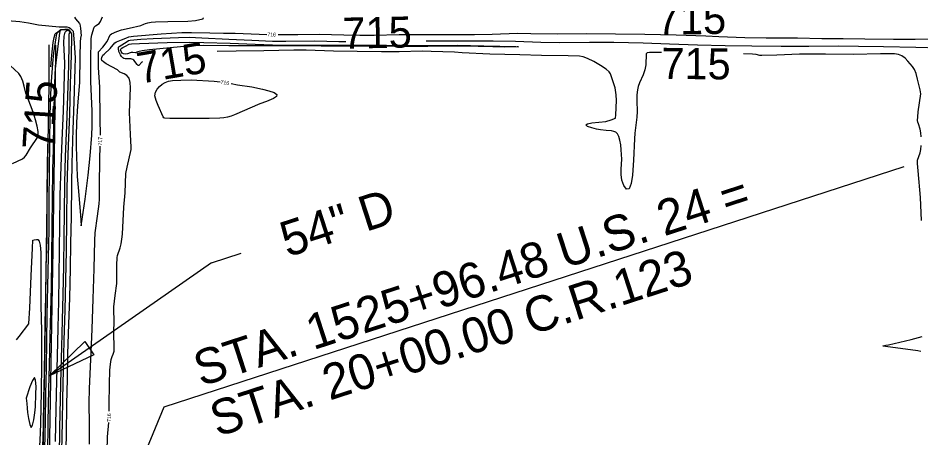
# Model space of a CAD drawing. Extents: x -468563856 to 36492962, y -306094093 to 11899197.
# Drawn here: x 1819091 to 1820050, y 530560 to 531006 of the extents above; entities that cross this region are included whole.
import ezdxf

# ---------------------------------------------------------------- set-up
doc = ezdxf.new("R2010")
doc.units = 0
for name, color, linetype in [('DT_X_Contour_Minor', 7, 'Continuous'), ('Level 19', 7, 'Continuous'), ('Level 40', 7, 'Continuous'), ('Level 56', 7, 'Continuous')]:
    doc.layers.add(name, color=color, linetype=linetype)

msp = doc.modelspace()

# ---------------------------------------------------------------- linework, layer by layer
at = {"layer": 'DT_X_Contour_Minor'}
for points in [[(1819080.31, 531003.25), (1819093.32, 531002.24), (1819102.49, 531000.93), (1819112.95, 530998.75), (1819123.96, 530997.52), (1819135.05, 530996.75), (1819143.11, 530996.66), (1819145.51, 530995.88), (1819147, 530994.88), (1819149.48, 530992.56), (1819149.75, 530992.14), (1819150.94, 530979.75), (1819151.96, 530963.61), (1819151.74, 530952.29), (1819150.58, 530917.11), (1819149.6, 530887.47), (1819148.32, 530851.32), (1819148.03, 530829.98), (1819147.6, 530794.77), (1819147.09, 530767.05), (1819146.57, 530739.96), (1819145.87, 530708.41), (1819145.06, 530681.06), (1819144.04, 530648.94), (1819143.44, 530622.57), (1819142.86, 530595.85), (1819142.3, 530563.39), (1819141.59, 530535.57)], [(1819151.2, 531006.75), (1819152.34, 531004.97), (1819156.66, 531000.33), (1819157.08, 530999.35), (1819157.7, 530995.22), (1819158.27, 530986.96), (1819158.04, 530986.37), (1819157.72, 530984.64), (1819157.41, 530980.57), (1819157.06, 530964.66), (1819156.66, 530937.45), (1819154.53, 530912.68), (1819153.43, 530895.11), (1819153.02, 530880.56), (1819153.11, 530869.68), (1819154.15, 530837.81), (1819155.4, 530821.95), (1819155.44, 530821.59)], [(1819155.44, 530821.59), (1819157.53, 530796.71), (1819158.48, 530785.45), (1819162.47, 530813.65), (1819165.84, 530839.19), (1819168.03, 530859.71), (1819169.82, 530881.48), (1819170.14, 530891.3), (1819169.9, 530907.06), (1819168.81, 530938.67), (1819168.68, 530960.15), (1819169.09, 530984.07), (1819169.72, 530988.06), (1819172.03, 530996.25), (1819173.62, 530997.52), (1819177.67, 531000.19), (1819179.04, 531002.13), (1819181.2, 531007.31)], [(1819178.76, 530881.74), (1819178.73, 530898.84), (1819178.05, 530932.58), (1819176.96, 530953.29), (1819176.97, 530969.95), (1819181.28, 530975.06), (1819186.16, 530980.98), (1819189.33, 530987.98), (1819190.6, 530989.13), (1819196.42, 530991.79), (1819201.22, 530993.46), (1819209.5, 530995.34), (1819221.72, 530997.98), (1819225.09, 530999.35), (1819226.84, 531000.16), (1819229.25, 531000.97), (1819232.69, 531001.61), (1819237.44, 531002), (1819250.3, 531002.27), (1819271.74, 531002.72), (1819279.97, 531003.52), (1819287.48, 531005.01), (1819288.3, 531005.54), (1819287.5, 531006.1)], [(1819138.56, 530685.04), (1819139.23, 530712.43), (1819139.82, 530742.62), (1819140.3, 530773.46), (1819140.66, 530798.58), (1819141.1, 530830.85), (1819141.84, 530859.05), (1819143.31, 530891.82), (1819144.33, 530923.36), (1819145.33, 530955.95), (1819145.79, 530978.81), (1819145.8, 530988.99), (1819146.41, 530990.98), (1819145.69, 530992.42), (1819144.59, 530993.77), (1819141.19, 530993.71), (1819136.58, 530993.47), (1819135.63, 530992.66), (1819132.23, 530989.11), (1819131.45, 530984.89), (1819129.14, 530968.96), (1819127.94, 530957.57), (1819126.46, 530938.57), (1819125.75, 530924.77), (1819125.23, 530902.82), (1819124.8, 530873.65), (1819124.46, 530842.84), (1819124.11, 530811.97), (1819123.95, 530780.38), (1819123.35, 530751.91), (1819122.79, 530721.27), (1819122.08, 530690.11), (1819121.64, 530664.16), (1819121.08, 530634.24), (1819120.55, 530606.52), (1819120, 530578.27), (1819119.3, 530547.97)], [(1819133.87, 530676.96), (1819134.57, 530705.41), (1819135.1, 530730.81), (1819135.5, 530760.39), (1819135.83, 530786.04), (1819136.27, 530818.03), (1819137, 530848.3), (1819138.05, 530876.44), (1819139.57, 530907.24), (1819140.31, 530932.33), (1819140.9, 530957.96), (1819140.03, 530979.7), (1819140.3, 530986.85), (1819141.34, 530990.85), (1819142.75, 530992.37), (1819144.74, 530993.05), (1819144.42, 530993.36), (1819136.72, 530993.07), (1819135.64, 530991.89), (1819135.16, 530987.28), (1819131.37, 530958.48), (1819130.62, 530951.92), (1819130.34, 530947.19), (1819129.58, 530922.95), (1819129.01, 530897.72), (1819128.5, 530866.1), (1819128.12, 530845.44), (1819127.55, 530812.9), (1819127.28, 530785.53), (1819126.84, 530750.76), (1819126.38, 530720.73), (1819125.75, 530693.9), (1819125.17, 530668.45), (1819124.48, 530637.31), (1819123.87, 530612.12), (1819123.04, 530576.32), (1819122.55, 530542.42)], [(1819126.13, 530954), (1819127.15, 530966.61), (1819128.7, 530979.97), (1819129.75, 530985.23), (1819130.96, 530989.1), (1819131.57, 530990.04), (1819133.36, 530991.07), (1819135.36, 530992.7), (1819136.7, 530993.74), (1819138.04, 530993.86), (1819144.9, 530993.87), (1819145.86, 530992.55), (1819148.05, 530989.13), (1819148.16, 530986.14), (1819147.78, 530966.46), (1819146.87, 530935.98), (1819145.87, 530903.96), (1819144.61, 530870.48), (1819143.79, 530850.11), (1819143.32, 530825.2), (1819142.89, 530791.28), (1819142.35, 530758.56), (1819141.82, 530728.05), (1819141.06, 530695.81), (1819140.09, 530663.49), (1819139.34, 530632.43), (1819138.61, 530601.67), (1819138.12, 530576.66), (1819137.58, 530546.32)], [(1819188.14, 530588.36), (1819188.26, 530595.02), (1819188.46, 530617.2), (1819189, 530631.93), (1819189.51, 530638.28), (1819190.3, 530643.24), (1819191.41, 530646.54), (1819192.55, 530649.08), (1819193.35, 530652.05), (1819193.56, 530656.29), (1819193.09, 530671.04), (1819193.38, 530685.6), (1819193.01, 530695.08), (1819193.2, 530699.41), (1819194.59, 530711.14), (1819196.19, 530724.05), (1819196.3, 530729.96), (1819196.22, 530743.67), (1819196.56, 530751.52), (1819197.01, 530753.64), (1819199.86, 530761.89), (1819200.86, 530766.11), (1819201.68, 530771.08), (1819202.23, 530776.54), (1819203.61, 530805), (1819204.98, 530820.18), (1819205.83, 530840.8), (1819207.14, 530847.62), (1819211.48, 530866.41), (1819211.62, 530868.72), (1819210.89, 530882.44), (1819209.74, 530905.56), (1819210.7, 530931.96), (1819210.41, 530937.61), (1819209.24, 530942.04), (1819206.95, 530944.92), (1819204.16, 530946.57), (1819199.36, 530948.48), (1819196.88, 530950.87), (1819185.04, 530957.46), (1819182, 530959.48), (1819180.35, 530961.01), (1819179.85, 530962.16), (1819180.36, 530964.11), (1819181.57, 530966.37), (1819182.91, 530967.73), (1819189.04, 530973.6), (1819194.2, 530979.75), (1819195.97, 530980.77), (1819201.29, 530982.72), (1819205.94, 530984.52), (1819208.97, 530986.15), (1819213.89, 530986.69), (1819243.47, 530989.1), (1819265.45, 530990.44), (1819275.62, 530990.7), (1819294.92, 530990.22), (1819309.48, 530989.81), (1819321.99, 530989.73), (1819347.55, 530988.68), (1819355.44, 530988.52)], [(1819367.44, 530988.41), (1819388.31, 530988.64), (1819411.18, 530988.73), (1819437.37, 530988.06), (1819454.31, 530987.73), (1819469.51, 530987.84), (1819496.24, 530988.38), (1819527.66, 530988.53), (1819559.81, 530988.48), (1819575.99, 530988.52), (1819594.74, 530988.91), (1819621.88, 530989.77), (1819636.04, 530989.7), (1819664.7, 530989.34), (1819695.1, 530989.44), (1819725.86, 530989.13), (1819757.08, 530988.76), (1819790.24, 530988.04), (1819821.59, 530987.14), (1819835.5, 530986.48), (1819863.05, 530985.14), (1819885.78, 530984.97), (1819918.92, 530984.85), (1819945.05, 530984.32), (1819967.53, 530984.12), (1819990.41, 530984), (1820020.89, 530983.63), (1820043.94, 530983.51), (1820075.99, 530983.99)], [(1819223.39, 530959.58), (1819222.72, 530959.08), (1819219.79, 530955.64), (1819218.85, 530955.52), (1819217.8, 530956.58), (1819214.49, 530961.32), (1819213.42, 530962.05), (1819211.06, 530962.6), (1819205.01, 530962.66), (1819203.76, 530963.08), (1819202.49, 530963.86), (1819201.27, 530965.06), (1819200.15, 530966.72), (1819198.53, 530970.54), (1819198.03, 530973.56), (1819198.16, 530975.07), (1819198.69, 530975.58), (1819207.19, 530981.09), (1819208.8, 530981.95), (1819210.36, 530982.35), (1819221.82, 530983.37), (1819234.92, 530984.08), (1819261.68, 530985.32), (1819273.2, 530985.57), (1819286.63, 530985.06), (1819315.28, 530983.65), (1819339.76, 530982.43), (1819361.52, 530981.46), (1819375.88, 530981.5), (1819406.59, 530981.85), (1819432.06, 530981.22), (1819439.59, 530981.06)], [(1819327.78, 530976.32), (1819315.06, 530976.36), (1819287.81, 530976.73), (1819276.23, 530976.47), (1819263.79, 530975.36), (1819231.13, 530972.14), (1819223.27, 530971.22), (1819218.42, 530970.07), (1819215.78, 530969.16), (1819213.39, 530969.29), (1819211.57, 530969.45), (1819210.25, 530969.04), (1819207.47, 530968.02), (1819205.14, 530967.65), (1819203.18, 530967.85), (1819201.83, 530968.82), (1819200.81, 530970.59), (1819200.31, 530972.38), (1819200.39, 530973.09), (1819200.78, 530973.68), (1819202.6, 530974.68), (1819205.36, 530976.12), (1819209.22, 530978.14), (1819211.79, 530978.54), (1819220.46, 530979.08), (1819249.57, 530979.86), (1819273.03, 530980.21), (1819288.82, 530979.87), (1819316.71, 530979.12), (1819343.03, 530978.11), (1819370.89, 530977.22), (1819398.1, 530977.16), (1819424.43, 530977.05), (1819453.87, 530977.09), (1819470.45, 530977.04), (1819494.09, 530976.79), (1819523.85, 530976.84), (1819557.73, 530977.24), (1819585.87, 530976.58), (1819619.93, 530975.73), (1819622.66, 530975.53), (1819621.32, 530975.34), (1819607.66, 530975.02), (1819595.52, 530975.25), (1819564.33, 530976.03), (1819553.32, 530976.23), (1819526.44, 530975.91), (1819500.02, 530975.7), (1819468.97, 530976.05), (1819442.86, 530976.15), (1819413.09, 530976.21), (1819385.99, 530976.37), (1819352.08, 530976.35), (1819327.78, 530976.32)], [(1819488.4, 530981.47), (1819488.78, 530981.48)], [(1819524.85, 530981.62), (1819546.69, 530981.85), (1819570.02, 530981.69), (1819595.74, 530981.59), (1819619.67, 530981.29), (1819646.62, 530980.33), (1819666.36, 530980.14), (1819698.01, 530980.47), (1819724.18, 530980.2), (1819755.23, 530979.76), (1819783.11, 530978.61), (1819812.82, 530977.62), (1819842.16, 530976.64), (1819870.43, 530976.38), (1819901.85, 530976.23), (1819931.2, 530976.23), (1819962.14, 530976.56), (1819983.87, 530976.21), (1820010.27, 530975.64), (1820044.52, 530975.05), (1820069.74, 530974.32)], [(1819774.46, 530969.5), (1819771.8, 530969.52), (1819761.82, 530969.31), (1819759.34, 530969.04), (1819758.42, 530968.06), (1819757.99, 530956.39), (1819757.06, 530950.87), (1819755.29, 530945.78), (1819751.16, 530937), (1819749.84, 530933.19), (1819749.09, 530929.79), (1819748.52, 530924.37), (1819748.57, 530918.03), (1819748.78, 530906.89), (1819748.53, 530900.68), (1819746.99, 530889.38), (1819746.23, 530883.73), (1819745.79, 530877.73), (1819745.04, 530855.08), (1819743.67, 530838.93), (1819742.32, 530830.18), (1819740.25, 530824.63), (1819737.44, 530824.37), (1819734.55, 530828.16), (1819732.41, 530833.92), (1819731.63, 530839.89), (1819731.79, 530845.64), (1819732.4, 530856.06), (1819731.88, 530865.89), (1819731.31, 530871.14), (1819730.5, 530876.17), (1819729.42, 530880.3), (1819728, 530883.05), (1819726.23, 530884.67), (1819724.1, 530885.58), (1819721.61, 530886.15), (1819716.02, 530886.7), (1819709.73, 530887.14), (1819705.56, 530887.89), (1819700.55, 530889.23), (1819696.17, 530890.88), (1819694.29, 530892.48), (1819696.17, 530893.7), (1819700.52, 530894.55), (1819715.68, 530896.15), (1819721.35, 530897.74), (1819725.74, 530899.47), (1819725.9, 530899.72), (1819726.19, 530903.3), (1819726.72, 530918.44), (1819726.49, 530924.43), (1819725.27, 530931.77), (1819723.35, 530938.23), (1819720.52, 530946.72), (1819719.13, 530948.99), (1819715.82, 530951.84), (1819709.88, 530955.65), (1819702.7, 530959.7), (1819696.17, 530963.02), (1819691.56, 530964.88), (1819687.67, 530965.6), (1819675.4, 530965.77), (1819647.32, 530966.08), (1819624.1, 530966.87), (1819592.33, 530967.75), (1819562.87, 530968.98), (1819554.84, 530969.57), (1819529.95, 530970.51), (1819520.57, 530970.64), (1819496.22, 530970.16), (1819477.33, 530969.92), (1819451.58, 530970.26), (1819426.21, 530970.73), (1819397.35, 530971.96), (1819384.05, 530971.89), (1819352.39, 530971.05), (1819323.11, 530970.72), (1819302.64, 530970.44)], [(1820041.23, 530954.39), (1820036.29, 530960.34), (1820033.24, 530963.43), (1820029.95, 530965.91), (1820026.41, 530967.35), (1820021.9, 530967.93), (1820007.09, 530967.81), (1819978.54, 530967.26), (1819948.77, 530967.52), (1819921.03, 530967.54), (1819897, 530966.61), (1819881.02, 530966.06), (1819878.95, 530966.33), (1819875.02, 530967.1), (1819871.25, 530967.51), (1819861.61, 530967.95)], [(1819085.52, 530851.42), (1819096.24, 530856.49), (1819098.29, 530858.3), (1819099.83, 530860.33), (1819104.43, 530868.13), (1819112.12, 530879.05), (1819112.76, 530881.63), (1819112.61, 530885.43), (1819111.64, 530891.03), (1819110.01, 530897.84), (1819107.88, 530904.96), (1819105.47, 530911.55), (1819099.5, 530926.12), (1819097.88, 530933.47), (1819096.37, 530939.02), (1819094.45, 530943.97), (1819092.17, 530947.23), (1819082.83, 530955.63)], [(1820050.46, 530879.72), (1820050.11, 530884.08), (1820049.45, 530887.93), (1820047.45, 530893.45), (1820046.68, 530895.42), (1820046.39, 530897.1), (1820046.69, 530901.19), (1820047.22, 530906.2), (1820049.99, 530925.41), (1820049.16, 530929.74), (1820046.57, 530941.22), (1820044.89, 530947.04), (1820043.14, 530951.28), (1820041.23, 530954.39)], [(1819317.67, 530936.3), (1819324.37, 530935.17), (1819339.75, 530932.91), (1819351.1, 530930.51), (1819357.61, 530928.84), (1819363.21, 530926.92), (1819366.25, 530924.79), (1819365.64, 530922.56), (1819362.52, 530920.43), (1819355.17, 530917.39), (1819348.29, 530914.87), (1819321.1, 530903.1), (1819317.52, 530901.78), (1819313.76, 530900.68), (1819309.86, 530899.98), (1819305.52, 530899.61), (1819294.26, 530899.36), (1819266.45, 530899.15), (1819252.54, 530899.14), (1819247.14, 530899.66), (1819246.33, 530900.09), (1819245.64, 530900.95), (1819240.12, 530913.07), (1819237.91, 530918.34), (1819236.7, 530923.33), (1819237.17, 530927.38), (1819238.97, 530930.61), (1819241.5, 530933.28), (1819244.3, 530935.6), (1819247.43, 530937.52), (1819251.07, 530938.9), (1819255.33, 530939.68), (1819264.25, 530940.15), (1819275.11, 530940.24), (1819299.62, 530939.06), (1819305.83, 530938.23)], [(1819117.67, 530550.74), (1819118.37, 530572.31), (1819118.88, 530602.07), (1819119.39, 530629.22), (1819119.75, 530655.31), (1819120.12, 530681.93), (1819120.75, 530710.58), (1819121.39, 530741.13), (1819122.15, 530771.23), (1819122.37, 530791.31), (1819122.4, 530823.97), (1819122.61, 530845.41), (1819122.87, 530872.07)], [(1819167.21, 530553.27), (1819167.2, 530574.75), (1819167, 530596.84), (1819167.3, 530612.44), (1819168.8, 530643.3), (1819169.94, 530675.58), (1819171.05, 530707.68), (1819172.19, 530739.54), (1819172.73, 530769.71), (1819173.33, 530777.95), (1819175.66, 530795.51), (1819177.5, 530808.61), (1819177.86, 530813.65), (1819178.02, 530827.98), (1819178.22, 530856.1), (1819178.54, 530869.74)], [(1820050.55, 530790.91), (1820049.53, 530815.45), (1820047.03, 530843.53), (1820046.54, 530851.64), (1820046.29, 530853.25), (1820046.43, 530855.07), (1820049.36, 530862.73), (1820050.08, 530866.43), (1820050.46, 530870.63)], [(1819089.62, 530664.24), (1819092.57, 530667.61), (1819102.74, 530681.28), (1819102.85, 530681.7), (1819103.73, 530697.78), (1819105.36, 530732.06), (1819106.74, 530761.74), (1819107.23, 530770.06), (1819108.47, 530770.57), (1819110.82, 530770.85), (1819112.27, 530770.68), (1819113.67, 530769.1), (1819114.77, 530764.77), (1819115.41, 530756.88), (1819115.67, 530736.61), (1819115.42, 530704.93), (1819115.93, 530682.55), (1819116.25, 530678.12), (1819116.39, 530668.38), (1819116.19, 530638.45), (1819115.91, 530609.13), (1819115.34, 530575.61), (1819114.91, 530565.52), (1819113.34, 530536.57)], [(1819135.25, 530539.31), (1819135.82, 530570.8), (1819136.42, 530601.29), (1819137.17, 530631.99), (1819137.73, 530656.62), (1819138.56, 530685.04)], [(1819131.23, 530556.26), (1819131.8, 530590.99), (1819132.58, 530621.18), (1819133.18, 530646.92), (1819133.87, 530676.96)], [(1820050.18, 530651.82), (1820046.88, 530652.48), (1820017.86, 530656.35), (1820009.74, 530657.55), (1820010.16, 530657.82), (1820012.97, 530658.45), (1820015.63, 530658.99), (1820039.71, 530664.59), (1820051.51, 530667.67)], [(1819099.99, 530602.38), (1819100.72, 530596.56), (1819100.99, 530591.77), (1819101.48, 530587.2), (1819102.45, 530580.63), (1819103.77, 530574.33), (1819105.29, 530571.26), (1819106.82, 530573.47), (1819108.21, 530579.39), (1819109.28, 530586.56), (1819109.93, 530593.09), (1819110.41, 530606.44), (1819110.44, 530614.57), (1819110.05, 530621.49), (1819108.85, 530624.29), (1819106.63, 530621.11), (1819104.01, 530614.42), (1819099.99, 530602.38)], [(1819185.85, 530546.09), (1819186.52, 530561.25), (1819187.64, 530576.36)]]:
    msp.add_lwpolyline(points, dxfattribs=at)
at = {"layer": 'Level 40'}
for p, q in [((1819296.63, 530746.01), (1819328.24, 530756.27)), ((1819296.63, 530746.01), (1819124.77, 530625.91)), ((1819124.77, 530625.91), (1819162.14, 530662.49)), ((1819162.14, 530662.49), (1819171.98, 530648.41)), ((1819171.98, 530648.41), (1819124.77, 530625.91))]:
    msp.add_line(p, q, dxfattribs=at)
msp.add_lwpolyline([(1819150.23, 530359.68), (1819246.6, 530593.19), (1820032.21, 530848.25)], dxfattribs=at)
at = {"layer": 'Level 56'}
for points in [[(1819117.15, 530463.97), (1819118.3, 530560.36), (1819120.08, 530660.34), (1819121.74, 530760.33), (1819122.45, 530810.32), (1819124.48, 530935.11), (1819124.58, 530977.45)], [(1819123.91, 530463.84), (1819125.06, 530560.22), (1819126.84, 530660.2), (1819128.5, 530760.19), (1819129.21, 530810.19), (1819131.24, 530934.97), (1819131.34, 530977.31)]]:
    msp.add_lwpolyline(points, dxfattribs=at)

# ---------------------------------------------------------------- texts
at = {"layer": 'Level 19'}
for s, height, rotation, p in [('715', 33, 0.93392, (1819769.85, 530988.09)), ('715', 33, 1.09435, (1819436.07, 530973.37)), ('716', 4, 358.85493, (1819356.05, 530986.51)), ('715', 33, 9.75747, (1819220.69, 530936.06)), ('715', 33, 359.47945, (1819774.34, 530941.38)), ('715', 33, 86.49371, (1819128.83, 530865.51)), ('716', 4, 350.39234, (1819306.14, 530936.23)), ('717', 4, 88.64803, (1819180.56, 530870.44)), ('716', 4, 89.03191, (1819189.95, 530576.97))]:
    msp.add_text(s, height=height, rotation=rotation, dxfattribs=at).set_placement(p)
at = {"layer": 'Level 40'}
for s, p in [('STA. 1525+96.48 U.S. 24 =', (1819285.55, 530614.41)), ('54" D', (1819377.33, 530751.69)), ('STA. 20+00.00 C.R.123', (1819302.92, 530560.9))]:
    msp.add_text(s, height=37.5, rotation=17.9864, dxfattribs=at).set_placement(p)

doc.saveas('drawing.dxf')
